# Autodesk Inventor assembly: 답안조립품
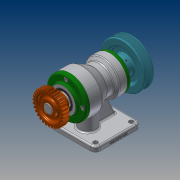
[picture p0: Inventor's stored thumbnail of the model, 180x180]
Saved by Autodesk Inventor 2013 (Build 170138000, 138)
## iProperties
Created: 2019-01
Part Number: 답안조립품
Document SubType Name: Assembly
Designer: Administrator
Author: Administrator
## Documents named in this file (15)
- C:\Users\Administrator\Desktop\490107V1045\답안조립품.iam
- C:\Users\Administrator\Desktop\490107V1045\본체.ipt
- C:\Users\Administrator\Desktop\490107V1045\뒤커버.ipt
- C:\Users\Administrator\Desktop\490107V1045\멈춤나사 M3.ipt
- C:\Users\Administrator\Desktop\490107V1045\베어링 6203.ipt
- C:\Users\Administrator\Desktop\490107V1045\베어링 6205.ipt
- C:\Users\Administrator\Desktop\490107V1045\볼트 M4.ipt
- C:\Users\Administrator\Desktop\490107V1045\스퍼기어.ipt
- C:\Users\Administrator\Desktop\490107V1045\앞커버.ipt
- C:\Users\Administrator\Desktop\490107V1045\오일 실 17 30 8.ipt
- C:\Users\Administrator\Desktop\490107V1045\오일 실 25 38 8.ipt
- C:\Users\Administrator\Desktop\490107V1045\축.ipt
- C:\Users\Administrator\Desktop\490107V1045\키 5 x 5 x 20.ipt
- C:\Users\Administrator\Desktop\490107V1045\키 6 x 6 x 18.ipt
- C:\Users\Administrator\Desktop\490107V1045\V-벨트풀리.ipt
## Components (1 placed, 1 different names)
1. V-벨트풀리:1 — 플러쉬:1
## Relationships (1: Flush 1)
- 플러쉬:1 [Flush]: V-벨트풀리:1
